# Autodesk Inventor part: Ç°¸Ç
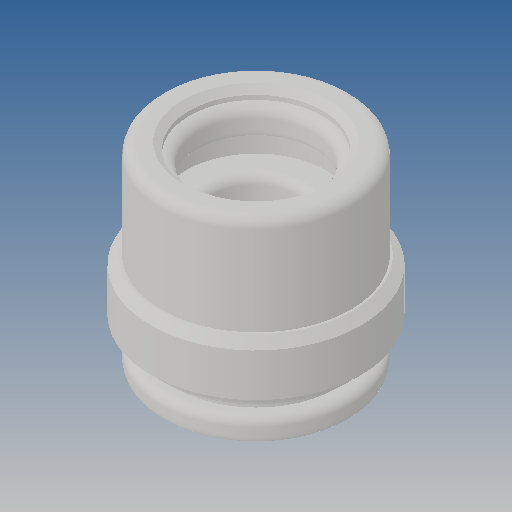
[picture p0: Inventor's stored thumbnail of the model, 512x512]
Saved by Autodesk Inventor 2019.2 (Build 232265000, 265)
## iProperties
Created: 2013-09
Part Number: Ç°¸Ç
Material: Ogólny
Document SubType Name: Modeling
Designer: CADENGINEERING4
Density: 1 g/cm^3
Appearance: Domyślna
Author: CADENGINEERING4
Revision Number: ÈÎºÎ
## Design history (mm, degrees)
feature "NONE"
node "Bryła1"
